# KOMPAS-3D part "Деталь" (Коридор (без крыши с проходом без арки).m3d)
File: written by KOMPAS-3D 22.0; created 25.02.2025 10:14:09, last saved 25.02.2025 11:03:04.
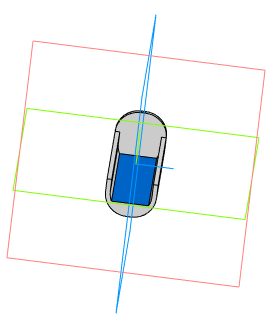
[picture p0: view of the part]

Document properties: Автор: Пользователь Windows; Полное имя файла: C:\Users\Student\Documents\Картошечка\База Сабнатика\Коридор\Коридор (без крыши с проходом без арки).m3d

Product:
- Part/product: Деталь
    Масса: 0.00858

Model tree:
1. Эскиз:1
2. Элемент выдавливания:1
     Расстояние 1 = 30
3. Эскиз:2  (with: Элемент выдавливания:1)
4. Элемент выдавливания:2
     Расстояние 2 = 5
5. Оболочка:1  (with: Элемент выдавливания:2)
     Толщина стенки 2 = 1
6. Эскиз:3  (with: Оболочка:1)
7. Элемент выдавливания:3
     Расстояние 1 = 28
8. Эскиз:4  (with: Оболочка:1)
9. Элемент выдавливания:4
     Расстояние 2 = 1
